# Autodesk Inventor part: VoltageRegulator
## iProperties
Shininess: 64.0
Length Units: 11272
Angle Units: 11279
Time Units: 11290
Mass Units: 11286
Length Display Precision: 3
Angle Display Precision: 2
Compacted: True
Part Number: VoltageRegulator
Document SubType Name: Modeling
Created: 2006-08
Designer: jpalmisano
Manufacturer: Standard
Standards Organization: Custom
Density: 0.0
Volumn: 0.0
Area: 0.0
PropertySet Name: Model Information
Control State: 0
Master: False
Checked Out: False
Author: jpalmisano
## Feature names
1. Extrusion1
2. Extrusion2
3. Extrusion3
4. Extrusion4
5. Chamfer1
